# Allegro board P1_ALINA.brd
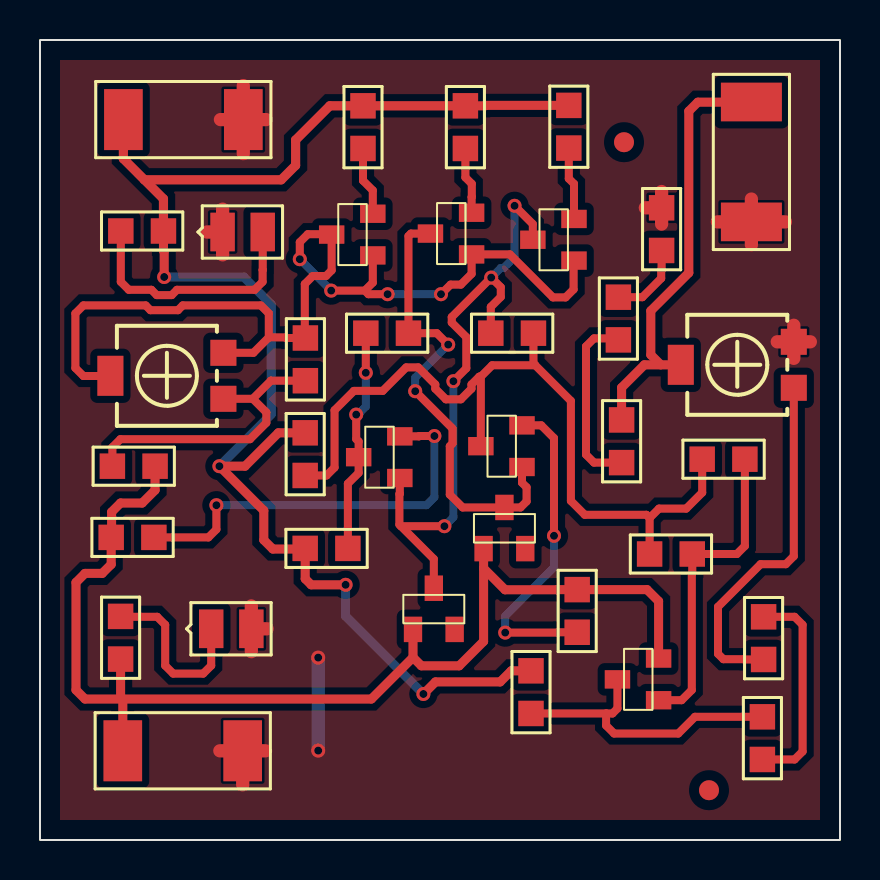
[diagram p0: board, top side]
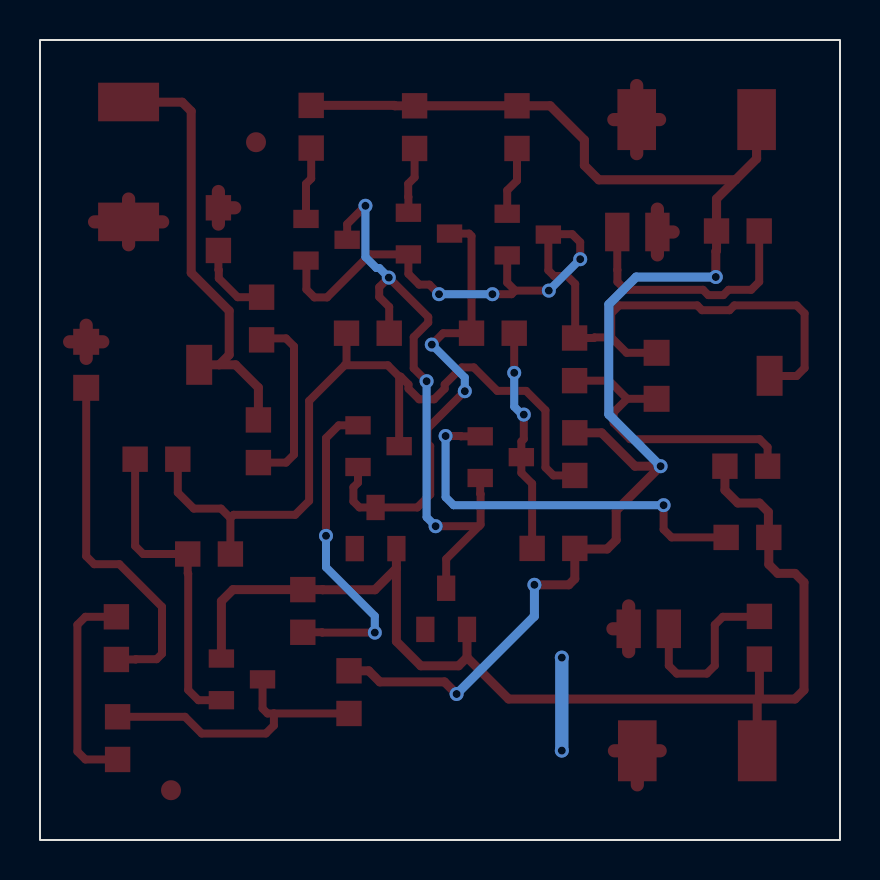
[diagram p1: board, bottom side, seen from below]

Outline 40 x 40 mm; copper layers: TOP, BOTTOM. Coordinates in mm from the lower left corner of the outline.
Outline path: rectangle 0,0 40,40

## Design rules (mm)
nets with their own width: min track width 0.4; nets N00566 N00570 N00574 N00648 N00689 N00735 N00812 N001181 N01285 N02107 N13335 N15152 N42140 N42144 N48070 N48898 N51295 N55134 N57759
nets with their own width: min track width 0.45; nets OUT+ V+ V-
nets with their own width: min track width 0.66; nets GND

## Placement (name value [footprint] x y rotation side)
C1  100p  [SMC0805]  30.48 14.3 0 top
C2  2.2n  [SMC0805]  22.54 25.34 0 top
C3  2.2n  [SMC0805]  16.29 25.34 0 top
D5  BZX84-C5V6  [TO236AA]  18.65 10.53 270 top
D6  BZX84-C5V6  [TO236AA]  22.18 14.57 270 top
D7  5V,LED,LED  [SMD0805]  9.13 30.4 0 top
D8  5V,LED,LED  [SMD0805]  8.56 10.56 0 top
J1  CON2  [SMR2512]  4.17 36.02 0 top
J2  CON2  [SMR2512]  4.14 4.46 0 top
J3  CON2  [SMR2512]  35.57 36.9 270 top
NOREF  -  [unnamed]  29.2 34.89 0 top
NOREF#2  -  [unnamed]  33.45 2.49 0 top
Q1  QBC856B  [TO236AA]  16.64 29.23 0 top
Q2  QBC856B  [TO236AA]  21.58 29.28 0 top
Q3  QBC856B  [TO236AA]  26.7 28.97 0 top
Q4  QBC846B  [TO236AA]  17.99 18.1 0 top
Q5  QBC846B  [TO236AA]  24.1 18.65 0 top
Q6  QBC846B  [TO236AA]  30.93 6.99 0 top
R1  1k  [SMR0805]  16.15 36.71 270 top
R2  2k  [SMR0805]  21.27 36.71 270 top
R3  2k  [SMR0805]  26.44 36.73 270 top
R4  2k  [SMR0805]  13.26 14.58 0 top
R5  2k  [SMR0805]  13.26 20.36 270 top
R6  150k  [SMR0805]  13.27 25.1 270 top
R8  15k  [SMR0805]  3.62 18.69 0 top
R9  220  [SMR0805]  4.04 30.45 0 top
R10  220  [SMR0805]  4.03 11.18 270 top
R11  33  [SMR0805]  3.56 15.13 0 top
R12  33  [SMR0805]  26.86 12.52 270 top
R13  10k  [TS53YL]  37.69 24.91 0 top
R14  500k  [TS53YL]  9.17 24.36 0 top
R15  2k  [SMR0805]  24.55 8.46 270 top
R16  10k  [SMR0805]  33.11 19.04 0 top
R17  22k  [SMR0805]  36.12 6.16 270 top
R18  1k  [SMR0805]  36.18 11.16 270 top
R19  10k  [SMR0805]  29.08 18.87 90 top
R20  1.5k  [SMR0805]  28.92 27.14 270 top
R21  1.5k  [SMR0805]  31.08 31.61 270 top

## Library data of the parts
C1-C3 = C
D5 D6 = BZX84-C5V6_0
D7 D8 = LED_0
J1-J3 = CON2
Q1-Q3 = QBC856B_0
Q4-Q6 = QBC846B_0
R1-R6 R8-R12 R15-R21 = R
R13 R14 = POT_0

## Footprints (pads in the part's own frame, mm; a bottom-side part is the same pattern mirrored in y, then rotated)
SMC0805
  rect 1.27x1.27 smd: 1(0,0) 2(2.134,0)
SMD0805
  rect 1.219x1.93 smd: A(2.007,0) C(0,0)
SMR0805
  rect 1.27x1.27 smd: 1(0,0) 2(2.134,0)
SMR2512
  rect 1.93x3.048 smd: 1(0,0) 2(5.994,0)
TO236AA
  rect 1.27x0.914 smd: 1(0,0) 2(0,2.083) 3(-2.057,1.041)
TS53YL
  rect 1.3x1.3 smd: 1(0,0) 3(0,-2.3)
  rect 1.3x2 smd: 2(-5.65,-1.15)
unnamed
  round 1 smd: (0,0)

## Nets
GND: D7.C D8.A J1.2 J2.2 J3.2 R13.1 R21.1
OUT+: J3.1 R13.2(WIPER) R19.2
V+: J1.1 R1.1 R2.1 R3.1 R4.1 R5.1 R9.2 R15.1
V-: D5.1 D6.1 J2.1 Q6.2(E) R8.2 R10.2 R11.1 R12.1
N00566: Q2.2(E) R2.2
N00570: Q3.2(E) R3.2
N00574: Q1.1 Q1.3 Q2.1 Q3.1 R6.1 R14.1 R14.2(WIPER)
N00648: C3.2 D6.3(C) Q2.3 Q5.1
N00689: C3.1 Q4.3 R4.2
N00735: C2.1 D5.3(C) Q3.3 Q4.1
N00812: C1.1 C2.2 Q5.3 R5.2 R16.1
N001181: Q1.2(E) R1.2
N01285: C1.2 Q6.1 R16.2
N02107: R6.2 R8.1 R14.3
N13335: Q6.3 R15.2 R17.1
N15152: R13.3 R18.2
N42140: R19.1 R20.2
N42144: R20.1 R21.2
N48070: Q4.2(E) R11.2
N48898: D7.A R9.1
N51295: Q5.2(E) R12.2
N55134: R17.2 R18.1
N57759: D8.C R10.1

Pads without a net: D5 2; D6 2

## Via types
v1: diameter 0.7, hole 0.4, TOP to BOTTOM, 22 vias

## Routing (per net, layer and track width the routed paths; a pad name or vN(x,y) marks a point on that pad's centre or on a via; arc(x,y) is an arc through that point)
GND: length 31.9
  TOP w0.66: J1.2 10.16,37.72 ; J1.2 10.16,34.32 ; J1.2 9.02,36.02 ; J1.2 11.31,36.02 ; J3.2 35.57,32.05 ; J3.2 35.57,29.76 ; J3.2 33.87,30.91 ; J3.2 37.27,30.91 ; J2.2 11.28,4.46 ; J2.2 8.99,4.46 ; J2.2 10.13,2.76 ; D8.A 10.57,11.7 ; D8.A 11.35,10.56 ; D8.A 10.57,9.42 ; R13.1 38.52,24.91 ; R13.1 36.86,24.91 ; R13.1 37.69,24.08 ; R13.1 37.69,25.74 ; 8.34,30.4 D7.C ; D7.C 9.13,31.54 ; D7.C 9.13,29.26 ; 30.27,31.61 R21.1 ; R21.1 31.08,32.42 ; R21.1 31.08,30.8
  BOTTOM w0.66: v1(13.91,9.12) v1(13.91,4.47)
OUT+: length 22
  TOP w0.45: R19.2 29.08,22.62 30.22,23.76 31.04,23.76 ; R13.2 31.04,23.76 ; 31.04,23.76 30.54,24.26 30.54,26.46 32.44,28.36 32.44,36.44 32.89,36.89 35.56,36.89 J3.1
V+: length 75.8
  TOP w0.45: v1(6.21,28.15) 6.21,29.43 6.17,29.46 R9.2 ; R5.1 11.92,20.36 10.25,18.69 v1(8.97,18.69) 11.19,16.47 11.19,15 11.64,14.55 13.23,14.55 R4.1 13.26,13.06 13.56,12.76 v1(15.28,12.76) ; v1(19.17,7.3) 19.77,7.91 23.01,7.91 23.56,8.46 R15.1 ; R2.1 22.26,36.71 22.28,36.73 R3.1
  TOP w0.457: 5.22,33.01 6.17,32.06 R9.2 ; 5.22,33.01 12.06,33.01 12.78,33.73 12.78,35 14.49,36.71 R1.1 R2.1 ; 5.22,33.01 4.17,34.06 J1.1
  BOTTOM w0.45: v1(19.17,7.3) 15.28,11.19 v1(15.28,12.76) ; v1(6.21,28.15) 10.19,28.15 11.56,26.78 11.56,21.28 v1(8.97,18.69)
V-: length 59.1
  TOP w0.45: D5.1 18.65,9.13 ; 18.65,9.13 19.07,8.71 20.96,8.71 22.18,9.93 22.18,13.58 ; 18.65,9.13 16.57,7.05 4.14,7.05 ; R8.2 5.75,17.49 5.11,16.85 4.03,16.85 3.58,16.4 3.58,15.15 R11.1 3.56,13.78 3.11,13.33 2.25,13.33 1.8,12.88 1.8,7.5 2.25,7.05 4.14,7.05 ; 22.18,13.58 23.25,12.51 25.86,12.51 25.87,12.52 R12.1 30.35,12.52 30.93,11.94 Q6.2 30.86,9.14 ; 22.18,13.58 D6.1 ; 4.14,7.05 J2.1 ; 4.14,7.05 4.03,7.16 R10.2
N00566: length 3.4
  TOP w0.4: R2.2 21.27,33.13 21.59,32.81 21.59,32.16 21.58,32.15 Q2.2
N00570: length 3.7
  TOP w0.4: Q3.2 26.7,32.81 26.44,33.07 R3.2
N00574: length 49.5
  TOP w0.4: v1(17.38,27.29) 16.42,27.29 16.24,27.47 ; Q1.1 16.64,27.87 16.24,27.47 ; 11.44,25.13 12.28,25.13 12.31,25.1 R6.1 13.24,25.13 13.24,27.8 13.64,28.2 14.3,28.2 14.58,28.48 Q1.3 14.56,30.29 13.39,30.29 12.99,29.89 v1(12.99,29.04) ; 11.44,25.13 11.44,26.33 11.04,26.73 7.14,26.73 6.9,26.49 5.52,26.49 5.28,26.73 2.17,26.73 1.77,26.33 1.77,23.6 2.17,23.2 3.51,23.2 R14.2 ; 11.44,25.13 10.67,24.36 R14.1 ; 16.24,27.47 v1(14.56,27.47) ; v1(20.05,27.29) 20.53,27.77 21.04,27.77 21.58,28.31 Q2.1 23.5,29.28 25.65,27.13 26.28,27.13 26.68,27.53 26.68,28.95 Q3.1
  BOTTOM w0.4: v1(20.05,27.29) v1(17.38,27.29) ; v1(14.56,27.47) v1(12.99,29.04)
N00648: length 23.3
  TOP w0.4: v1(20.41,24.77) 19.84,25.34 C3.2 18.42,30.2 18.55,30.32 Q2.3 ; v1(18.76,22.44) 20.62,20.57 20.62,19.83 20.49,19.69 20.49,17.27 21.13,16.63 D6.3 24.03,16.63 24.33,16.93 24.33,17.64 24.1,17.87 Q5.1
  BOTTOM w0.4: v1(20.41,24.77) 18.76,23.12 v1(18.76,22.44)
N00689: length 11.3
  TOP w0.4: v1(15.81,21.27) 15.81,20.05 15.93,19.93 Q4.3 15.93,18.36 15.39,17.82 R4.2 ; C3.1 v1(16.29,23.36)
  BOTTOM w0.4: v1(15.81,21.27) 15.89,21.27 16.29,21.67 v1(16.29,23.36)
N00735: length 31.8
  TOP w0.4: 18.05,15.69 19.69,14.05 D5.3 ; 18.05,15.69 v1(20.22,15.69) ; 18.05,15.69 17.97,15.77 17.97,17.3 17.99,17.32 Q4.1 ; v1(20.67,22.94) 21.32,23.59 21.32,25.14 20.59,25.87 20.59,26.15 v1(22.56,28.12) 23.04,27.64 23.04,27.15 22.54,26.65 C2.1 ; Q3.3 24.64,30.8 v1(23.73,31.71)
  BOTTOM w0.4: v1(20.22,15.69) 20.67,16.14 v1(20.67,22.94) ; v1(23.73,31.71) 23.73,29.15 23.18,28.6 23.04,28.6 v1(22.56,28.12)
N00812: length 40.6
  TOP w0.4: 22.04,23.17 22.61,23.74 24.76,23.74 ; 22.04,23.17 Q5.3 ; 22.04,23.17 21.97,23.17 21.57,22.78 21.57,22.57 21.04,22.04 20.3,22.04 19.77,22.57 19.77,22.78 18.91,23.63 18.31,23.63 17.14,22.45 15.7,22.45 14.73,21.49 14.73,18.63 14.33,18.23 R5.2 ; 24.76,23.74 24.67,23.83 C2.2 ; 24.76,23.74 26.55,21.95 26.55,16.95 27.24,16.26 30.32,16.26 30.48,16.1 ; C1.1 30.48,16.1 ; 30.48,16.1 30.95,16.57 32.31,16.57 33.11,17.37 R16.1
N001181: length 3.5
  TOP w0.4: R1.2 16.15,32.97 16.64,32.48 Q1.2
N01285: length 15.8
  TOP w0.4: R16.2 35.24,14.7 34.84,14.3 C1.2 32.61,13.34 32.59,13.31 32.59,7.5 32.08,6.99 Q6.1
N02107: length 15.1
  TOP w0.4: 10.64,22.06 11.55,22.97 R6.2 ; 10.64,22.06 11.32,21.38 11.32,20.86 10.5,20.04 4.02,20.04 3.62,19.64 R8.1 ; 10.64,22.06 R14.3
N13335: length 14.8
  TOP w0.4: R17.1 32.75,6.16 31.91,5.33 28.71,5.33 28.31,5.72 28.31,6.32 28.31,6.33 ; 28.31,6.33 28.62,6.33 28.87,6.58 Q6.3 ; 28.31,6.33 R15.2
N15152: length 18
  TOP w0.4: R18.2 35.22,9.03 35.2,9.04 34.17,9.04 33.9,9.31 33.9,11.66 36.03,13.79 37.29,13.79 37.69,14.19 R13.3
N42140: length 9.2
  TOP w0.4: R20.2 28.85,25.08 27.7,25.08 27.3,24.68 27.3,19.27 27.7,18.87 R19.1
N42144: length 3.9
  TOP w0.4: R20.1 30.12,27.14 31.06,28.08 31.06,28.49 31.08,28.51 R21.2
N48070: length 20.4
  TOP w0.4: v1(19.72,20.2) 18.97,20.2 18.95,20.18 Q4.2 ; v1(8.82,16.74) 8.82,15.53 8.42,15.13 R11.2
  BOTTOM w0.4: v1(8.82,16.74) 19.32,16.74 19.72,17.14 v1(19.72,20.2)
N48898: length 12.7
  TOP w0.4: D7.A 11.14,28.51 11.13,28.5 11.13,27.91 10.73,27.51 6.85,27.51 6.58,27.25 5.84,27.25 5.57,27.51 4.44,27.51 4.04,27.91 R9.1
N51295: length 16.2
  TOP w0.4: R12.2 25.9,10.39 25.88,10.37 v1(23.26,10.37) ; v1(25.7,15.21) 25.7,20.09 25.06,20.73 Q5.2
  BOTTOM w0.4: v1(25.7,15.21) 25.7,13.64 23.26,11.2 v1(23.26,10.37)
N55134: length 10.6
  TOP w0.4: R17.2 37.73,4.03 38.13,4.43 38.13,10.76 37.73,11.16 R18.1
N57759: length 8.9
  TOP w0.4: R10.1 4.05,11.16 5.86,11.16 6.26,10.76 6.26,8.72 6.66,8.32 8.16,8.32 8.56,8.72 D8.C

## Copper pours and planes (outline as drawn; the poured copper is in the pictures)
GND on TOP: 1,1 1,39 39,39 39,1 ; 13 cut-outs

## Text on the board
Ref Des/Assembly Top: Drugea Alina-Nicoleta | 433D, CEF- Pr 2025-2026
NCLEGEND-1-2: FIGURE | FINISHED_SIZE | 0.4 | DRILL CHART: TOP to BOTTOM | ALL UNITS ARE IN MILLIMETERS | PLATED | QTY | 20 | TOTAL HOLES:
